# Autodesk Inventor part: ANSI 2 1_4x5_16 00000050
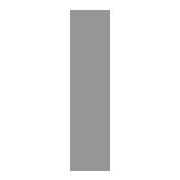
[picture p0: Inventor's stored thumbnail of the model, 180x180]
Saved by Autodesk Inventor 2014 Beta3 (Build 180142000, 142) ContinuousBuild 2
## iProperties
_CCFamilyMember: 149
_CCFamilyDisplayName: ANSI AISC (Rectangular) - Flat Bar Steel
_FrameMemberDoc: Frame Member File
_Version: 15.0.0
_GetPNFromCC: 1
Created: 2010-11
Part Number: ANSI 2 1_4x5_16 00000050
Material: Steel, Mild
Description: Flat Bar Steel
Document SubType Name: Modeling
Standard: ANSI
Designer: Beta-8540w
Standards Organization: ANSI
Language: en-US
Size Designation: 2 1/4x5/16
Categories: <MemberInstance><Categories><Category DisplayName="Structural Shapes" InternalName="089c4875-fa83-4c05-b084-43b9cc11f5ed" Mnemonic="GRDR"><CategoryParameter Dis
Stock Number: 2 1/4x5/16
Density: 7.86 g/cm^3
Appearance: Steel
IsCustomPart: 1
G_L: 9.325 in
G_W: 0.313 in
G_H: 2.250 in
Author: Beta-8540w
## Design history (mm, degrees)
node "Start plane"
node "End plane"
node "Driven Length"
  sketch "Sketch3"
    geometry: L1 (0, 0)-(10, 0) reference
    constraints: 2 end point, 1 horizontal
  workplane "Work Plane3"
  sketch "Sketch4"
    geometry: L1 (-2, 0)-(12, 0) reference; L2 (-40.005, 236.864)-(40.005, 236.864) reference
    dimensions: "d9" = 236.86413 distance between parallel lines of L1 L2 (derived)
sketch "Sweep Path"
  geometry: L1 through (25.4, 40.279) direction (-1, 0); L2 through (112.121, 127) direction (-1, 0); 9 other entities
  constraints: 10 horizontal
node "Orientation Work Plane"
feature "Body" dims "d10" = 0
body "Solid1"
sketch "Sketch"
  geometry: L1 (3.969, -28.575)-(-3.969, -28.575); L2 (-3.969, -28.575)-(-3.969, 28.575); L3 (-3.969, 28.575)-(3.969, 28.575); L4 (3.969, 28.575)-(3.969, -28.575); L5 (-6, 0)-(8, 0); L6 (0, -30)-(0, 40); L7 (0, 54)-(0, -44); L8 (-9.2, 0)-(13.2, 0)
  constraints: 16 end point, 2 collinear, 2 parallel, 1 horizontal, 1 perpendicular
  dimensions: "d0" = 57.15 distance between parallel lines of L3 L1 (= G_W); "d1" = 7.9375 distance between parallel lines of L4 L2 (= G_H); "d4" = 3.96875 distance between parallel lines of L6 L4 (= 0.5 x d1); "d5" = 28.575 distance between parallel lines of L5 L3 (= 0.5 x d0)
other parameters: "G_W" = 57.15 [user parameter; used in 1 equation term], "G_H" = 7.9375 [user parameter; used in 1 equation term], "G_L" = 236.86413 (= d9) [user parameter], "G_OFFSET_START" = 0 [user parameter; used in 1 equation term], "G_OFFSET_END" = 0 [user parameter; used in 1 equation term], "d6" = 0 (computed from G_OFFSET_START), "d7" = 236.86413 (= G_OFFSET_END + B_L), "B_L" = 236.86413 [user parameter; used in 1 equation term], "d8" = 90 deg
